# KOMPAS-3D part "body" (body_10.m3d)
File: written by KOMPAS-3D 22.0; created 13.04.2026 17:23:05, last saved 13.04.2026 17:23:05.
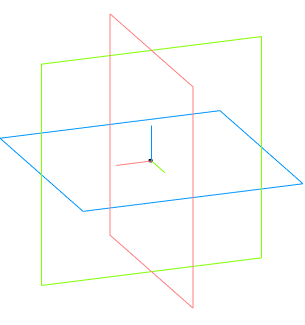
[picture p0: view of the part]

Document properties: Автор: Andrey; Полное имя файла: C:\Users\User1\Documents\body_10.m3d

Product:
- Part/product: body

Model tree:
1. Операция без истории:1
